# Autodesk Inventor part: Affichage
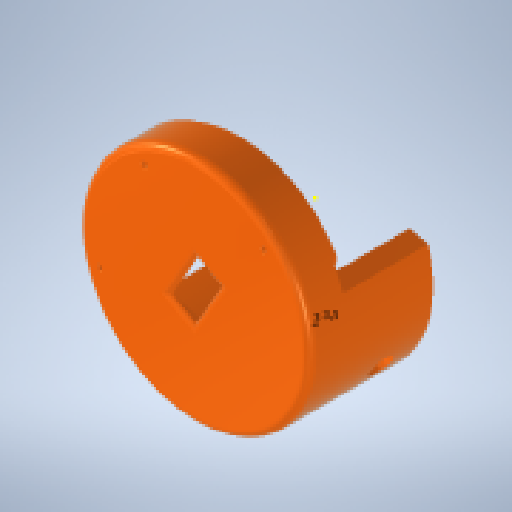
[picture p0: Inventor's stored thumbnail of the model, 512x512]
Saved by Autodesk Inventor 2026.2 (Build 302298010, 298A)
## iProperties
Created: 2026-09
Part Number: Affichage
Material: Générique
Document SubType Name: Modeling
Designer: mel
Density: 1 g/cm^3
Appearance: Lisse - Orange clair
Mass: 570.949 g
Surface Area: 708.308 cm^2
Volume: 570.949 cm^3
Author: mel
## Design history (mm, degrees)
sketch "Esquisse1"
  geometry: L1 (69.392, 14.472)-(12.15, 29.154) reference; L2 (-38.968, -1.094)-(-53.65, -58.336) reference; L3 (-52.387, -63.471)-(-36.547, -1.715) reference; L4 (11.529, 26.733)-(73.285, 10.893) reference; C1 r 75 at (1.715, -11.529); A1 r 42 centre (1.715, -11.529) between (12.15, 29.154) and (-38.968, -1.094) reference; A2 r 72.5 centre (1.715, -11.529) between (69.392, 14.472) and (-53.65, -58.336) reference; A3 r 75 centre (1.715, -11.529) between (73.285, 10.893) and (-52.387, -63.471) reference; A4 r 39.5 centre (1.715, -11.529) between (11.529, 26.733) and (-36.547, -1.715) reference; 3 further points
  constraints: 1 centre point, 1 coincident, 1 concentric
extrude "Extrusion1" new body sketch "Esquisse1" distance "d0" = 25; taper "d1" = 0 deg
sketch "Esquisse2"
  geometry: L1 (-67.677, 26.001)-(-10.435, 40.683) reference; L2 (40.683, 10.435)-(55.365, -46.807) reference; L3 (-56.33, 29.428)-(-10.559, 41.167); L4 (41.167, 10.559)-(52.907, -35.211); A1 r 42 centre (0, 0) between (40.683, 10.435) and (-10.435, 40.683) reference; A2 r 72.5 centre (0, 0) between (55.365, -46.807) and (-67.677, 26.001) reference; A3 r 42.5 centre (0, 0) between (41.167, 10.559) and (-10.559, 41.167); A4 r 72 centre (0, 0) between (62.06, -36.504) and (-61.868, 36.828); A5 r 5 centre (-57.572, 34.271) between (-61.868, 36.828) and (-56.33, 29.428); A6 r 5 centre (57.75, -33.969) between (52.907, -35.211) and (62.06, -36.504); 3 further points
  constraints: 10 point on circle, 4 centre point, 4 end point, 4 tangent, 2 point on line, 1 equal radius, 3 other
  dimensions: "d2" = 0.5 radial gap between concentric circles of A2 A4; "d3" = 5 radius of A5
extrude "Extrusion2" join sketch "Esquisse2" distance "d4" = 5; taper "d5" = 0 deg
sketch "Esquisse3"
  geometry: L1 (-9.814, 38.261)-(-71.57, 22.421) reference; L2 (54.102, -51.943)-(38.261, 9.814) reference; A1 r 39.5 centre (0, 0) between (38.261, 9.814) and (-9.814, 38.261) reference; A2 r 75 centre (0, 0) between (-71.57, 22.421) and (54.102, -51.943) reference; A3 r 65 centre (0, 0) between (-59.816, 25.436) and (51.087, -40.189); 1 further point
  constraints: 2 point on circle, 2 point on line, 1 centre point
  dimensions: "d6" = 10 radial gap between concentric circles of A2 A3
extrude "Extrusion3" join sketch "Esquisse3" distance "d7" = 55; taper "d8" = 0 deg
fillet "Congé1" dims "d9" = 5
sketch "Esquisse4"
  geometry: C1 r 1.25 at (-61.458, -17.293) reference; C2 r 1.25 at (-32.61, 54.889) reference; C3 r 1.25 at (44.578, 45.705) reference; 1 further point
hole "Perçage1" sketch "Esquisse4" at (-61.458, -17.293), (-32.61, 54.889), (44.578, 45.705) diameter "d10" = 3; stored, may be unused: countersink angle "d14" = 90 deg, drill point angle "d16" = 118 deg; dims "d11" = 6, "d12" = 4, "d13" = 2, "d15" = 12
sketch "Esquisse5"
  geometry: L1 (49.372, -51.718)-(52.387, -63.471) reference; L2 (-73.285, 10.893)-(-61.531, 13.907) reference; L3 (51.192, -46.74)-(39.452, -0.97) reference; L4 (-12.274, 29.639)-(-58.044, 17.899) reference; L5 (49.372, -51.718)-(51.726, -48.033); L6 (-61.531, 13.907)-(-59.079, 17.746); A1 r 75 centre (-1.715, -11.529) between (52.387, -63.471) and (-73.285, 10.893) reference; A2 r 65 centre (-1.715, -11.529) between (-61.531, 13.907) and (49.372, -51.718) reference; A3 r 42.5 centre (-1.715, -11.529) between (39.452, -0.97) and (-12.274, 29.639) reference; A4 r 5 centre (-59.287, 22.742) between (-63.583, 25.3) and (-58.044, 17.899) reference; A5 r 72 centre (-1.715, -11.529) between (60.345, -48.033) and (-63.583, 25.3) reference; A6 r 5 centre (56.035, -45.498) between (51.192, -46.74) and (60.345, -48.033) reference; A7 r 65 centre (-1.715, -11.529) between (-61.531, 13.907) and (49.372, -51.718) reference; 1 further point
  constraints: 4 end point, 2 point on circle, 1 parallel
extrude "Extrusion4" cut sketch "Esquisse5" distance "d17" = 22; taper "d18" = 0 deg
sketch "Esquisse6"
  geometry: L1 (20.189, 63.668)-(-20.167, 63.668); L2 (-55.167, 28.668)-(-55.167, -28.627); L3 (-40.167, -43.627)-(40.189, -43.627); L4 (55.189, -28.627)-(55.189, 28.668); A1 r 35 centre (20.189, 28.668) between (55.189, 28.668) and (20.189, 63.668); A2 r 35 centre (-20.167, 28.668) between (-20.167, 63.668) and (-55.167, 28.668); A3 r 15 centre (40.189, -28.627) between (40.189, -43.627) and (55.189, -28.627); A4 r 15 centre (-40.167, -28.627) between (-55.167, -28.627) and (-40.167, -43.627); 3 further points
  constraints: 8 end point, 8 point on circle, 8 tangent, 4 centre point, 4 point on line, 2 equal radius, 2 parallel, 1 horizontal, 1 perpendicular
  dimensions: "d19" = 35 radius of A1; "d22" = 15 radius of A3 (derived)
extrude "Extrusion5" cut sketch "Esquisse6" stored distance "d20" = 22; taper "d21" = 0 deg
sketch "Esquisse7"
  geometry: L1 (174.809, 564.39)-(-575.862, -734.261) reference; L2 (-43.121, -24.643)-(29.859, 101.612); L3 (-36.658, -13.462)-(-6.631, 38.484); L4 (-6.631, 38.484)-(36.658, 13.462); L5 (36.658, 13.462)-(6.631, -38.484); L6 (6.631, -38.484)-(-36.658, -13.462); C1 r 75 at (0, 0) reference; 1 further point
  constraints: 10 end point, 3 parallel, 1 midpoint, 1 perpendicular, 1 point on line
  dimensions: "d29" = 30 distance from line of C1.centre L6; "d30" = 30 distance from line of L4 C1.centre; "d31" = 25 distance from line of L2 C1.centre; "d32" = 25 distance from line of C1.centre L5
extrude "Extrusion6" cut sketch "Esquisse7" extent not by distance; stored distance "d23" = 0; taper "d24" = 0 deg
sketch "Esquisse8"
  geometry: L1 (-16.3, -10.214)-(0.716, 19.222); L2 (0.716, 19.222)-(16.3, 10.214); L3 (16.3, 10.214)-(-0.716, -19.222); L4 (-0.716, -19.222)-(-16.3, -10.214); L5 (-6.631, 38.484)-(-36.658, -13.462) reference; L6 (6.631, -38.484)-(-36.658, -13.462) reference; L7 (-6.631, 38.484)-(36.658, 13.462) reference; L8 (36.658, 13.462)-(6.631, -38.484) reference; 1 further point
  constraints: 8 end point, 3 parallel, 1 perpendicular
  dimensions: "d25" = 18 distance of L1.end L2.end; "d26" = 34 distance between parallel lines of L2 L4; "d27" = 13 distance between parallel lines of L4 L6; "d28" = 13 distance between parallel lines of L7 L2 (derived); "d33" = 16 distance between parallel lines of L1 L5; "d34" = 16 distance between parallel lines of L8 L3 (derived)
node "Plan de construction1"
extrude "Extrusion7" join sketch "Esquisse8" stored distance "d35" = 10; taper "d36" = 0 deg
fillet "Congé2" dims "d37" = 5
sketch "Esquisse9"
  geometry: L1 (-8.803, 47.719)-(-42.303, 47.719) reference; L2 (-8.803, 47.719)-(-8.803, 12.319) reference; L3 (-8.803, 12.319)-(-42.303, 12.319) reference; L4 (-42.303, 47.719)-(-42.303, 37.019) reference; L5 (-42.303, 23.019)-(-42.303, 12.319) reference; L6 (-38, 51)-(-12, 51) reference; C1 r 1.5 at (-11.303, 45.219) reference; C2 r 1.5 at (-11.303, 14.819) reference; C3 r 1.5 at (-39.803, 14.819) reference; C4 r 1.5 at (-39.803, 45.219) reference; C5 r 1.25 at (-11.303, 45.219); C6 r 1.25 at (-11.303, 14.819); C7 r 1.25 at (-39.803, 45.219); C8 r 1.25 at (-39.803, 14.819); 1 further point
  constraints: 4 centre point, 4 coincident
  dimensions: "d47" = 2.5 diameter of C5 (= d48); "d48" = 2.5 diameter of C6 (= d49); "d49" = 2.5 diameter of C7; "d50" = 2.5 diameter of C8 (= d49)
extrude "Extrusion8" join sketch "Esquisse9" distance "d51" = 10; taper "d52" = 0 deg
node "Plan de construction4"
  node "Plan de construction3"
sketch "Esquisse10"
  geometry: C1 r 7.5 at (-0.289, -31.006); 1 further point
  constraints: 1 centre point
  dimensions: "d54" = 15 diameter of C1
extrude "Extrusion9" cut sketch "Esquisse10" extent not by distance; stored distance "d55" = 0; taper "d56" = 0 deg
sketch "Esquisse11"
  geometry: 1 further point
sketch "Esquisse12"
  geometry: L1 (-24.737, -68.681)-(47.911, -50.047) reference; L2 (-30.203, -47.371)-(-24.737, -68.681) reference; L3 (42.445, -28.737)-(-30.203, -47.371) reference; L4 (47.911, -50.047)-(42.445, -28.737) reference; L5 (-25.049, -57.404)-(-18.753, -55.79) reference; L6 (-15.847, -55.044)-(-14.878, -54.796) reference; L7 (-14.878, -54.796)-(-14.133, -57.702) reference; L8 (-14.133, -57.702)-(-12.195, -57.205) reference; L9 (-12.195, -57.205)-(-11.698, -59.142) reference; L10 (-11.698, -59.142)-(32.859, -47.713) reference; L11 (32.859, -47.713)-(31.617, -42.87) reference; L12 (31.617, -42.87)-(33.558, -42.372) reference; L13 (36.456, -41.629)-(42.756, -40.013) reference; L14 (31.617, -42.87)-(30.375, -38.027) reference; L15 (30.375, -38.027)-(-14.183, -49.456) reference; L16 (-14.183, -49.456)-(-13.686, -51.393) reference; L17 (-13.686, -51.393)-(-15.623, -51.89) reference; L18 (-15.623, -51.89)-(-14.878, -54.796) reference; A1 r 1.5 centre (-17.3, -55.417) between (-15.847, -55.044) and (-18.753, -55.79) reference; A2 r 1.5 centre (-17.3, -55.417) between (-18.753, -55.79) and (-15.847, -55.044) reference; A3 r 1.5 centre (35.034, -42.106) between (33.558, -42.372) and (36.456, -41.629) reference; A4 r 1.5 centre (35.034, -42.106) between (36.456, -41.629) and (33.558, -42.372) reference; 1 further point
  node "Référence22"
node "Plan de construction5"
extrude "Extrusion10" join sketch "Esquisse12" stored distance "d57" = 10; taper "d58" = 0 deg
sketch "Esquisse13"
  geometry: L1 (-34, 47)-(-16, 47) reference; L2 (-16, 47)-(-16, 13) reference; L3 (-16, 13)-(-34, 13) reference; L4 (-34, 13)-(-34, 47) reference; L5 (0, 0)-(-50, 0) reference; L6 (0, 60)-(0, 0) reference; L7 (-50, 60)-(0, 60) reference; L8 (-50, 0)-(-50, 60) reference; L9 (4.621, -6.998)-(-67.601, 13.226) reference; L10 (-20.369, 0)-(4.621, -6.998) reference; L11 (-20.369, 0)-(-50, 8.297) reference; L12 (-67.601, 13.226)-(-50, 8.297) reference; C1 r 1.25 at (-39.803, 14.819) reference; C2 r 1.25 at (-11.303, 14.819) reference; C3 r 1.25 at (-39.803, 45.219) reference; C4 r 1.25 at (-11.303, 45.219) reference; 3 further points
extrude "Extrusion11" join sketch "Esquisse13" stored distance "d59" = 10; taper "d60" = 0 deg
sketch "Esquisse14"
  geometry: C1 r 7.5 at (61.458, -17.293) reference; C2 r 7.5 at (32.61, 54.889) reference; C3 r 8 at (61.458, -17.293); C4 r 8 at (32.61, 54.889); 1 further point
  constraints: 2 centre point, 2 coincident
  dimensions: "d61" = 16 diameter of C3; "d62" = 16 diameter of C4
extrude "Extrusion12" cut sketch "Esquisse14" stored distance "d63" = 10; taper "d64" = 0 deg
sketch "Esquisse15"
  geometry: L1 (-13.99, -66.374)-(19.867, -69.702) reference; L2 (19.867, -69.702)-(22.304, -44.911) reference; L3 (21.309, -44.813)-(22.304, -44.911) reference; L4 (21.309, -44.813)-(-10.558, -41.681) reference; L5 (-11.553, -41.583)-(-10.558, -41.681) reference; L6 (-11.553, -41.583)-(-13.99, -66.374) reference; L7 (33.281, -45.99)-(22.304, -44.911); L8 (22.304, -44.911)-(20.303, -65.269); L9 (20.303, -65.269)-(31.28, -66.348); L10 (31.28, -66.348)-(33.281, -45.99); L11 (-17.465, -40.901)-(-11.553, -41.583); L12 (-11.553, -41.583)-(-14.884, -70.472); L13 (-14.884, -70.472)-(-20.795, -69.791); L14 (-20.795, -69.791)-(-17.465, -40.901); L15 (-13.99, -66.374)-(-14.389, -66.178); C1 r 70 at (0, 0) reference; 5 further points
  constraints: 18 end point, 4 parallel, 2 perpendicular, 1 point on line, 3 other
node "Point de construction1"
extrude "Extrusion13" join sketch "Esquisse15" stored distance "d65" = 10; taper "d66" = 0 deg
sketch "Esquisse16"
  geometry: L1 (-45.05, 20.45)-(-45.05, 0) reference; L2 (0, 0)-(-45.05, 0) reference; L3 (-45.05, 0)-(6.218, 0); L4 (6.218, 0)-(6.302, 20.45); L5 (67.571, 20.45)-(-66.353, 20.45) reference; L6 (-45.05, 20.45)-(6.302, 20.45); L7 (0, 20.45)-(0, 0) reference; C1 r 1.05 at (3.95, 15.65) reference; C2 r 1.05 at (3.95, 4.25) reference; C3 r 1.05 at (-43.05, 15.65) reference; C4 r 1.05 at (-43.05, 4.25) reference; C5 r 2 at (-43.05, 15.65); C6 r 2 at (-43.05, 4.25); C7 r 2.286 at (3.95, 4.25); C8 r 2.332 at (3.95, 15.65); 4 further points
  constraints: 6 end point, 4 centre point, 4 coincident, 4 tangent, 1 collinear, 1 horizontal, 1 point on line
extrude "Extrusion14" cut sketch "Esquisse16" distance "d67" = 5; taper "d68" = 0 deg
sketch "Esquisse17"
  geometry: L1 (0.017, 20.45)-(0.017, -0.55) reference; L2 (-5.951, 20.45)-(-5.951, 0) reference; L3 (-5.951, 20.45)-(0, 20.45) reference; L4 (0, 0)-(-5.951, 0) reference; L5 (-4.858, 0)-(-4.668, 20.45); C1 r 1.998 at (-1.981, 4.25); C2 r 1.998 at (-1.981, 15.65); 3 further points; 2 other entities
  constraints: 2 centre point, 2 coincident, 2 end point, 2 point on line, 2 tangent, 2 other
extrude "Extrusion15" cut sketch "Esquisse17" distance "d69" = 5; taper "d70" = 0 deg
sketch "Esquisse18"
  geometry: L1 (-4.668, 20.45)-(0, 20.45) reference; L2 (0, 20.45)-(0, -0.55) reference; L3 (-4.668, 20.45)-(-4.858, 0) reference; L4 (0, -0.55)-(-0.82, -0.55) reference; L5 (0, 0)-(-4.858, 0) reference; C1 r 1.75 at (-1.981, 15.65); C2 r 1.5 at (-1.981, 4.25); 3 further points; 2 other entities
  constraints: 2 centre point, 2 coincident, 2 other
  dimensions: "d71" = 3.5 diameter of C1; "d72" = 3 diameter of C2
extrude "Extrusion16" cut sketch "Esquisse18" stored distance "d73" = 10; taper "d74" = 0 deg
sketch "Esquisse20"
  geometry: L1 (0, 5)-(20.45, 5) reference; L2 (0, 0)-(0, 5) reference; L3 (0, 0)-(20.45, 0) reference; L4 (20.45, 5)-(20.45, 0) reference; 1 further point
extrude "Extrusion17" cut sketch "Esquisse20" distance "d75" = 1; taper "d76" = 0 deg
sketch "Esquisse21"
  geometry: C1 r 1 at (0, 0); C2 r 1.5 at (0, -11.4) reference; C3 r 1 at (0, -11.4); C4 r 1 at (-47.014, 0); C5 r 1 at (-47.014, -11.4); 12 further points; 9 other entities
  constraints: 4 centre point, 4 coincident, 2 horizontal alignment, 7 other
  dimensions: "d77" = 2 diameter of C1; "d78" = 2 diameter of C3; "d79" = 2 diameter of C4; "d80" = 2 diameter of C5
extrude "Extrusion18" cut sketch "Esquisse21" stored distance "d81" = 19; taper "d82" = 0 deg
node "Solide1"
node "Référence1"
node "Référence2"
node "Référence3"
node "Référence4"
node "Référence5"
node "Référence6"
node "Référence7"
node "Référence8"
node "Référence9"
node "Référence10"
node "Référence11"
node "Boucle projetée1"
node "Référence12"
node "Référence13"
node "Référence14"
node "Référence15"
node "Référence16"
node "Référence17"
node "Référence18"
node "Référence19"
node "Référence20"
node "Référence21"
node "Plan de construction2"
feature "ീ耀ു耀ൂ耀ൃ耀ൄ耀൅耀െ耀േ耀"
node "Boucle projetée2"
node "Boucle projetée3"
node "Référence23"
node "Référence24"
node "Référence25"
node "Référence26"
node "Référence27"
node "Référence28"
node "Référence29"
node "Référence30"
node "Référence31"
node "Référence32"
node "Référence33"
node "Référence34"
node "Référence35"
node "Boucle projetée4"
node "Référence36"
node "Référence37"
node "Référence38"
node "Référence39"
node "Référence40"
other parameters: "d53" = 90 deg
